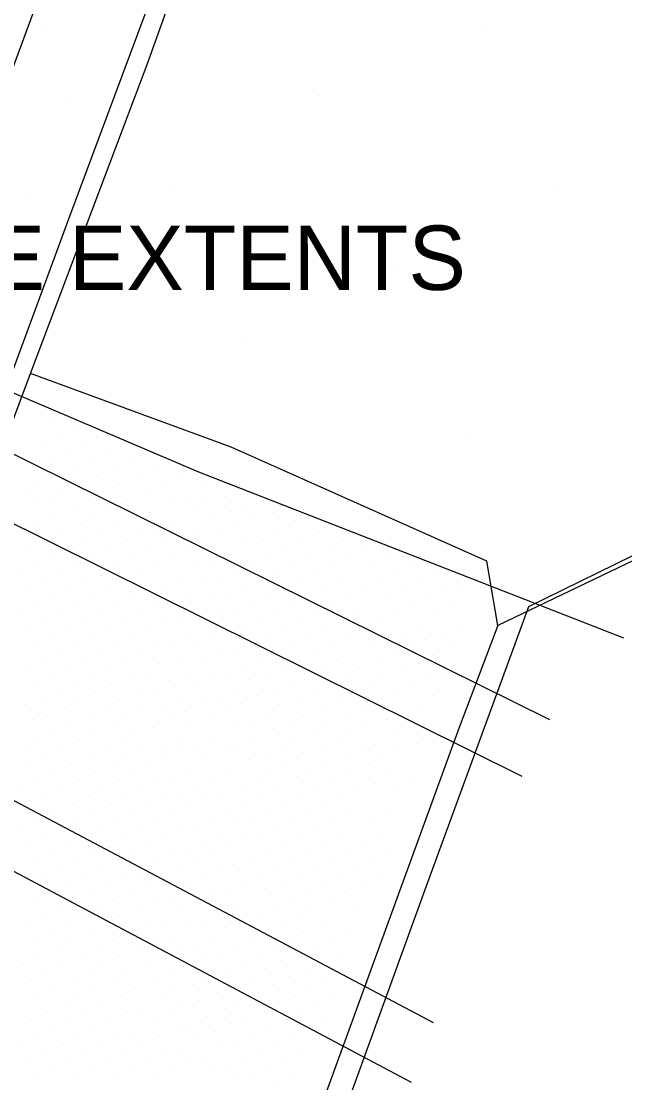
# Model space of a CAD drawing. Extents: x 1729983 to 1730242, y 468641 to 469019.
# Drawn here: x 1730163.18 to 1730180.05, y 468849.56 to 468879.25 of the extents above; entities that cross this region are included whole.
import ezdxf

# ---------------------------------------------------------------- set-up
doc = ezdxf.new("R2010")
doc.units = 0
for name, color, linetype in [('Default', 7, 'Continuous'), ('S_Bridge_Abutment_Bottom', 7, 'Continuous'), ('S_Curb_Type_1', 7, 'Continuous'), ('S_Ground_SpotElevation', 7, 'Continuous'), ('S_Misc_MiscFeature', 7, 'Continuous'), ('S_Roadway_Edge_Pavement', 7, 'Continuous'), ('S_Roadway_Painted_Lines', 7, 'Continuous'), ('S_Roadway_Sidewalks', 7, 'Continuous'), ('S_Text', 7, 'Continuous')]:
    doc.layers.add(name, color=color, linetype=linetype)

# ---------------------------------------------------------------- blocks, each defined once
blk = doc.blocks.new('POINT_DISPLAY')
at = {"layer": 'Default'}
blk.add_line((0, 0), (0, 0), dxfattribs=at)

msp = doc.modelspace()

# ---------------------------------------------------------------- linework, layer by layer
at = {"layer": 'S_Bridge_Abutment_Bottom'}
msp.add_lwpolyline([(1730181.425, 468864.71), (1730176.506, 468862.351), (1730175.427, 468859.495), (1730170.121, 468844.945), (1730162.576, 468824.377), (1730156.015, 468806.678), (1730146.892, 468781.991), (1730136.8, 468754.596), (1730127.192, 468728.47), (1730129.433, 468723.646)], dxfattribs=at)
at = {"layer": 'S_Curb_Type_1'}
msp.add_lwpolyline([(1730095.691, 468641.415), (1730095.909, 468646.136), (1730096.354, 468653.521), (1730096.818, 468653.995), (1730097.198, 468655.848), (1730096.66, 468657.036), (1730097.062, 468660.797), (1730098.243, 468671.757), (1730099.533, 468680.946), (1730101.556, 468692.14), (1730103.524, 468700.629), (1730106.497, 468712.327), (1730109.421, 468721.771), (1730114.404, 468736.003), (1730118.96, 468748.434), (1730124.347, 468762.755), (1730131.22, 468781.92), (1730136.349, 468795.804), (1730142.854, 468813.477), (1730149.849, 468832.496), (1730156.774, 468851.574), (1730163.434, 468869.402), (1730166.697, 468878.04), (1730172.479, 468894.171)], dxfattribs=at)
at = {"layer": 'S_Misc_MiscFeature'}
for p, q in [((1730150.177, 468873.465), (1730177.95, 468859.726)), ((1730177.188, 468858.129), (1730149.57, 468871.846)), ((1730147.288, 468865.747), (1730174.698, 468851.254)), ((1730174.087, 468849.573), (1730146.688, 468864.106))]:
    msp.add_line(p, q, dxfattribs=at)
for points in [[(1730180.027, 468861.998), (1730168.149, 468866.641), (1730159.874, 468870.164), (1730150.627, 468874.508)], [(1730180.75, 468864.535), (1730177.366, 468862.873), (1730174.461, 468854.957), (1730171.273, 468846.168), (1730167.811, 468836.657), (1730164.365, 468827.147), (1730154.502, 468800.309), (1730151.107, 468790.853), (1730144.524, 468772.905), (1730140.96, 468763.264), (1730137.54, 468754.064), (1730134.249, 468745.295), (1730130.903, 468736.495), (1730127.535, 468727.691), (1730129.089, 468724.341)]]:
    msp.add_lwpolyline(points, dxfattribs=at)
at = {"layer": 'S_Roadway_Edge_Pavement'}
msp.add_lwpolyline([(1730169.443, 468886.971), (1730164.503, 468873.715), (1730156.499, 468852.01), (1730147.717, 468828.276), (1730138.371, 468802.607), (1730128.942, 468777.012), (1730117.481, 468745.727), (1730111.874, 468730.709), (1730108.888, 468721.988), (1730105.794, 468711.827), (1730102.94, 468700.647), (1730101.123, 468692.177), (1730099.16, 468681.419), (1730097.818, 468671.805), (1730096.586, 468660.812), (1730096.168, 468657.103), (1730095.956, 468653.708), (1730095.867, 468652.572), (1730095.424, 468646.027), (1730095.252, 468641.367)], dxfattribs=at)
at = {"layer": 'S_Roadway_Painted_Lines'}
msp.add_lwpolyline([(1730094.799, 468656.256), (1730095.17, 468660.96), (1730096.083, 468669.985), (1730097.638, 468680.767), (1730099.581, 468691.95), (1730101.134, 468699.687), (1730104.772, 468714.073), (1730108.651, 468727.01), (1730112.542, 468738.83), (1730119.789, 468759.429), (1730137.203, 468807.807), (1730148.896, 468839.717), (1730160.486, 468871.271), (1730175.799, 468912.851), (1730190.41, 468952.883), (1730200.037, 468978.351)], dxfattribs=at)
at = {"layer": 'S_Roadway_Sidewalks'}
msp.add_lwpolyline([(1730176.506, 468862.351), (1730176.202, 468864.149), (1730169.049, 468867.338), (1730163.434, 468869.402)], dxfattribs=at)

# ---------------------------------------------------------------- block references
at = {"layer": 'S_Ground_SpotElevation'}
for p in [(1730163.786, 468879.057), (1730176.122, 468879.076), (1730171.509, 468877.18), (1730164.534, 468877.016), (1730167.412, 468874.677), (1730178.15, 468874.551), (1730163.449, 468874.405), (1730173.576, 468872.279), (1730169.407, 468870.366), (1730164.05, 468868.182), (1730164.634, 468867.892), (1730164.189, 468867.668), (1730165.293, 468867.636), (1730175.614, 468867.761), (1730163.742, 468867.455), (1730164.847, 468867.458), (1730166.041, 468867.438), (1730163.995, 468866.997), (1730164.461, 468867.167), (1730165.55, 468867.123), (1730166.634, 468867.123), (1730163.552, 468866.782), (1730164.674, 468866.729), (1730165.088, 468866.959), (1730165.719, 468866.713), (1730166.203, 468866.9), (1730167.315, 468866.882), (1730164.229, 468866.513), (1730165.273, 468866.52), (1730166.432, 468866.458), (1730166.856, 468866.694), (1730167.541, 468866.451), (1730167.965, 468866.659), (1730163.31, 468866.16), (1730163.639, 468866.347), (1730164.369, 468866.163), (1730164.868, 468866.272), (1730165.93, 468866.294), (1730167.083, 468866.257), (1730168.214, 468866.199), (1730169.248, 468866.168), (1730163.966, 468865.93), (1730165.056, 468865.834), (1730165.449, 468866.105), (1730166.16, 468865.842), (1730166.661, 468866.008), (1730167.796, 468865.97), (1730168.861, 468865.948), (1730163.509, 468865.75), (1730164.642, 468865.607), (1730165.672, 468865.668), (1730166.77, 468865.523), (1730167.336, 468865.782), (1730167.974, 468865.576), (1730168.325, 468865.774), (1730169.045, 468865.537), (1730169.474, 468865.718), (1730170.217, 468865.514), (1730163.679, 468865.267), (1730164.107, 468865.369), (1730165.211, 468865.457), (1730166.39, 468865.399), (1730167.464, 468865.266), (1730168.603, 468865.346), (1730169.661, 468865.306), (1730170.834, 468865.286), (1730163.183, 468865.034), (1730164.827, 468865.178), (1730165.389, 468864.983), (1730165.907, 468865.212), (1730167.022, 468865.045), (1730168.131, 468865.009), (1730169.24, 468865.106), (1730170.382, 468865.058), (1730171.53, 468864.965), (1730163.888, 468864.703), (1730164.302, 468864.916), (1730164.986, 468864.803), (1730166.149, 468864.75), (1730166.517, 468864.882), (1730167.202, 468864.64), (1730167.651, 468864.849), (1730168.81, 468864.9), (1730169.454, 468864.658), (1730169.952, 468864.77), (1730171.041, 468864.715), (1730172.196, 468864.754), (1730163.429, 468864.548), (1730164.111, 468864.331), (1730164.607, 468864.516), (1730165.22, 468864.35), (1730165.684, 468864.545), (1730166.759, 468864.426), (1730167.853, 468864.415), (1730168.326, 468864.587), (1730169.007, 468864.35), (1730170.152, 468864.348), (1730170.579, 468864.557), (1730171.22, 468864.327), (1730171.765, 468864.572), (1730172.822, 468864.408), (1730163.623, 468864.103), (1730165.805, 468864.04), (1730166.283, 468864.231), (1730166.939, 468864.029), (1730167.383, 468864.234), (1730168.532, 468864.147), (1730169.718, 468864.137), (1730170.815, 468864.125), (1730171.859, 468864.101), (1730172.323, 468864.285), (1730172.984, 468864.046), (1730173.513, 468864.289), (1730163.185, 468863.909), (1730164.277, 468863.809), (1730164.726, 468864.01), (1730165.418, 468863.761), (1730166.536, 468863.758), (1730168.048, 468863.989), (1730169.224, 468863.87), (1730170.335, 468863.952), (1730171.519, 468863.803), (1730173.731, 468863.842), (1730174.161, 468864.018), (1730174.783, 468863.772), (1730163.369, 468863.479), (1730163.833, 468863.629), (1730164.946, 468863.582), (1730166.065, 468863.562), (1730167.226, 468863.495), (1730167.676, 468863.695), (1730168.339, 468863.55), (1730168.75, 468863.694), (1730169.364, 468863.494), (1730169.962, 468863.685), (1730170.967, 468863.698), (1730172.15, 468863.575), (1730173.221, 468863.568), (1730174.372, 468863.591), (1730175.424, 468863.494), (1730164.015, 468863.213), (1730164.452, 468863.389), (1730165.57, 468863.408), (1730166.729, 468863.338), (1730167.89, 468863.246), (1730168.983, 468863.212), (1730170.098, 468863.242), (1730170.53, 468863.362), (1730171.265, 468863.193), (1730171.656, 468863.364), (1730172.794, 468863.38), (1730173.841, 468863.354), (1730174.996, 468863.353), (1730163.56, 468863.044), (1730164.669, 468862.992), (1730165.18, 468863.134), (1730165.835, 468862.917), (1730166.323, 468863.083), (1730166.913, 468862.933), (1730167.444, 468863.039), (1730168.523, 468863.067), (1730169.595, 468863.026), (1730170.684, 468862.988), (1730171.926, 468862.948), (1730172.393, 468863.111), (1730173.46, 468863.099), (1730174.069, 468862.894), (1730174.611, 468863.117), (1730175.231, 468862.894), (1730163.184, 468862.77), (1730164.262, 468862.734), (1730165.357, 468862.742), (1730166.522, 468862.655), (1730167.66, 468862.585), (1730168.096, 468862.807), (1730168.684, 468862.644), (1730169.204, 468862.761), (1730169.817, 468862.572), (1730170.235, 468862.798), (1730171.486, 468862.75), (1730172.477, 468862.715), (1730173.659, 468862.635), (1730174.721, 468862.638), (1730163.386, 468862.309), (1730163.83, 468862.516), (1730164.509, 468862.263), (1730164.923, 468862.517), (1730166.093, 468862.437), (1730166.707, 468862.25), (1730167.132, 468862.476), (1730168.342, 468862.434), (1730169.426, 468862.297), (1730170.469, 468862.328), (1730170.922, 468862.514), (1730172.05, 468862.435), (1730173.19, 468862.499), (1730174.334, 468862.385), (1730175.479, 468862.334), (1730163.993, 468862.128), (1730165.121, 468862.094), (1730165.631, 468862.234), (1730166.277, 468862.037), (1730167.88, 468862.127), (1730168.446, 468861.973), (1730168.916, 468862.171), (1730170.067, 468862.081), (1730171.162, 468862.04), (1730171.63, 468862.211), (1730172.279, 468861.97), (1730172.796, 468862.184), (1730173.444, 468862.005), (1730173.81, 468862.165), (1730174.464, 468861.951), (1730174.99, 468862.124), (1730163.564, 468861.891), (1730164.676, 468861.88), (1730165.8, 468861.861), (1730166.898, 468861.843), (1730167.437, 468861.93), (1730168.092, 468861.763), (1730169.159, 468861.687), (1730169.573, 468861.848), (1730170.745, 468861.799), (1730171.878, 468861.839), (1730172.959, 468861.862), (1730174.048, 468861.815), (1730175.204, 468861.737), (1730163.812, 468861.404), (1730164.247, 468861.642), (1730164.948, 468861.385), (1730165.386, 468861.608), (1730166.428, 468861.569), (1730167.65, 468861.485), (1730168.694, 468861.499), (1730169.794, 468861.465), (1730170.25, 468861.638), (1730170.958, 468861.401), (1730171.407, 468861.553), (1730172.004, 468861.385), (1730173.682, 468861.531), (1730174.674, 468861.518), (1730163.353, 468861.195), (1730164.5, 468861.157), (1730165.526, 468861.093), (1730165.987, 468861.28), (1730167.052, 468861.296), (1730168.223, 468861.329), (1730169.412, 468861.25), (1730170.447, 468861.236), (1730171.544, 468861.202), (1730172.649, 468861.148), (1730173.244, 468861.342), (1730173.824, 468861.169), (1730174.282, 468861.289), (1730163.969, 468861.032), (1730164.667, 468860.781), (1730165.084, 468860.863), (1730166.195, 468860.85), (1730166.651, 468861.042), (1730167.287, 468860.818), (1730167.828, 468861.027), (1730168.461, 468860.856), (1730168.926, 468861.035), (1730169.534, 468860.847), (1730170.033, 468860.988), (1730171.106, 468861), (1730172.265, 468860.888), (1730173.322, 468860.89), (1730174.555, 468860.835), (1730174.991, 468861.019), (1730163.573, 468860.752), (1730164.2, 468860.578), (1730165.257, 468860.482), (1730165.711, 468860.696), (1730166.865, 468860.599), (1730168.005, 468860.67), (1730169.178, 468860.536), (1730170.287, 468860.496), (1730170.707, 468860.733), (1730171.349, 468860.532), (1730171.787, 468860.732), (1730172.993, 468860.697), (1730174.013, 468860.68), (1730163.81, 468860.28), (1730164.793, 468860.277), (1730165.926, 468860.255), (1730166.399, 468860.428), (1730167.525, 468860.336), (1730168.247, 468860.19), (1730168.731, 468860.333), (1730169.316, 468860.177), (1730169.768, 468860.385), (1730170.943, 468860.264), (1730172.061, 468860.225), (1730172.515, 468860.413), (1730173.135, 468860.217), (1730173.551, 468860.439), (1730174.685, 468860.389), (1730163.283, 468860.147), (1730164.38, 468860.043), (1730165.543, 468859.967), (1730166.603, 468860.001), (1730167.093, 468860.136), (1730167.757, 468859.945), (1730168.902, 468859.942), (1730170.022, 468859.932), (1730170.403, 468860.129), (1730171.62, 468860.016), (1730172.683, 468860.031), (1730173.831, 468859.921), (1730174.232, 468860.121), (1730163.496, 468859.713), (1730163.907, 468859.801), (1730164.557, 468859.62), (1730165.058, 468859.787), (1730166.118, 468859.735), (1730167.323, 468859.71), (1730168.488, 468859.715), (1730169.566, 468859.687), (1730170.665, 468859.669), (1730171.06, 468859.795), (1730172.242, 468859.815), (1730173.391, 468859.733), (1730164.117, 468859.387), (1730165.221, 468859.415), (1730165.737, 468859.556), (1730166.378, 468859.311), (1730166.854, 468859.504), (1730167.904, 468859.496), (1730169.087, 468859.535), (1730170.206, 468859.466), (1730171.317, 468859.453), (1730171.72, 468859.53), (1730172.399, 468859.288), (1730172.816, 468859.545), (1730174.045, 468859.501), (1730163.314, 468859.002), (1730163.63, 468859.2), (1730164.806, 468859.151), (1730165.947, 468859.114), (1730167.094, 468859.024), (1730167.532, 468859.212), (1730168.157, 468859.003), (1730168.591, 468859.215), (1730169.221, 468858.993), (1730169.705, 468859.144), (1730170.456, 468858.982), (1730170.8, 468859.129), (1730172.011, 468859.19), (1730173.092, 468859.024), (1730173.608, 468859.278), (1730174.239, 468859.049), (1730163.895, 468858.73), (1730164.333, 468858.962), (1730165.535, 468858.856), (1730166.572, 468858.914), (1730167.66, 468858.869), (1730168.874, 468858.863), (1730170.002, 468858.776), (1730171.082, 468858.798), (1730171.576, 468858.963), (1730172.692, 468858.953), (1730173.713, 468858.815), (1730163.408, 468858.546), (1730164.572, 468858.496), (1730165.07, 468858.657), (1730165.734, 468858.426), (1730166.159, 468858.665), (1730166.818, 468858.42), (1730167.25, 468858.635), (1730168.337, 468858.622), (1730169.525, 468858.616), (1730170.593, 468858.44), (1730171.681, 468858.475), (1730172.24, 468858.627), (1730172.877, 468858.506), (1730173.321, 468858.659), (1730164.094, 468858.318), (1730165.252, 468858.254), (1730166.384, 468858.201), (1730167.464, 468858.122), (1730167.917, 468858.366), (1730169.005, 468858.331), (1730169.778, 468858.128), (1730170.119, 468858.27), (1730170.867, 468858.123), (1730171.208, 468858.27), (1730172.342, 468858.25), (1730173.456, 468858.171), (1730163.219, 468857.859), (1730163.674, 468858.073), (1730164.303, 468857.889), (1730164.801, 468858.048), (1730165.915, 468858.024), (1730167.02, 468857.945), (1730168.079, 468857.866), (1730168.602, 468858.08), (1730169.315, 468857.89), (1730170.362, 468857.808), (1730171.957, 468857.973), (1730173.074, 468857.946), (1730174.102, 468857.946), (1730163.887, 468857.642), (1730165.061, 468857.561), (1730165.489, 468857.773), (1730166.122, 468857.586), (1730166.604, 468857.745), (1730167.202, 468857.569), (1730167.696, 468857.648), (1730168.312, 468857.518), (1730168.767, 468857.632), (1730169.882, 468857.641), (1730171.005, 468857.593), (1730171.473, 468857.788), (1730172.203, 468857.549), (1730172.563, 468857.71), (1730173.685, 468857.765), (1730163.418, 468857.448), (1730164.611, 468857.345), (1730165.699, 468857.352), (1730166.737, 468857.34), (1730167.883, 468857.3), (1730169.024, 468857.206), (1730169.429, 468857.449), (1730170.597, 468857.424), (1730171.737, 468857.307), (1730163.644, 468856.996), (1730164.12, 468857.175), (1730164.668, 468856.915), (1730165.261, 468857.166), (1730166.333, 468857.135), (1730167.436, 468857.098), (1730168.59, 468857.003), (1730169.705, 468856.942), (1730170.122, 468857.188), (1730170.762, 468856.978), (1730171.26, 468857.12), (1730171.848, 468856.94), (1730172.39, 468857.092), (1730173.405, 468857.09), (1730163.198, 468856.778), (1730164.338, 468856.742), (1730165.36, 468856.646), (1730165.811, 468856.839), (1730166.577, 468856.636), (1730166.979, 468856.9), (1730168.143, 468856.799), (1730169.166, 468856.81), (1730170.349, 468856.666), (1730171.452, 468856.669), (1730173.051, 468856.882), (1730163.881, 468856.528), (1730164.895, 468856.472), (1730166.13, 468856.446), (1730167.197, 468856.447), (1730167.694, 468856.594), (1730168.715, 468856.542), (1730169.424, 468856.376), (1730169.882, 468856.559), (1730170.555, 468856.312), (1730171.007, 468856.517), (1730171.646, 468856.316), (1730172.104, 468856.387), (1730173.263, 468856.42), (1730163.367, 468856.215), (1730164.514, 468856.176), (1730165.608, 468856.163), (1730166.797, 468856.178), (1730167.785, 468856.112), (1730168.263, 468856.284), (1730168.98, 468856.17), (1730170.142, 468856.069), (1730171.128, 468856.017), (1730172.327, 468856.063), (1730172.722, 468856.231), (1730163.59, 468855.77), (1730164.048, 468855.975), (1730164.649, 468855.833), (1730165.165, 468855.956), (1730165.889, 468855.807), (1730166.302, 468855.931), (1730167.004, 468855.737), (1730167.431, 468855.978), (1730168.073, 468855.763), (1730168.547, 468855.944), (1730169.678, 468855.901), (1730170.682, 468855.808), (1730171.789, 468855.789), (1730173.047, 468855.749), (1730173.377, 468856), (1730164.238, 468855.522), (1730165.318, 468855.587), (1730166.474, 468855.456), (1730167.668, 468855.497), (1730168.785, 468855.482), (1730169.098, 468855.662), (1730170.262, 468855.572), (1730171.414, 468855.5), (1730172.481, 468855.513), (1730163.293, 468855.213), (1730163.831, 468855.31), (1730164.444, 468855.142), (1730164.93, 468855.304), (1730165.99, 468855.306), (1730167.123, 468855.225), (1730168.318, 468855.286), (1730169.359, 468855.179), (1730169.831, 468855.352), (1730170.434, 468855.189), (1730170.968, 468855.367), (1730171.577, 468855.132), (1730172.073, 468855.276), (1730172.697, 468855.142), (1730173.167, 468855.356), (1730163.959, 468854.981), (1730165.111, 468854.889), (1730165.541, 468855.109), (1730166.213, 468854.826), (1730166.762, 468855.099), (1730167.737, 468855.039), (1730168.884, 468854.992), (1730169.983, 468854.983), (1730171.151, 468854.901), (1730172.226, 468854.914), (1730163.572, 468854.731), (1730164.62, 468854.743), (1730165.739, 468854.671), (1730166.85, 468854.593), (1730167.337, 468854.775), (1730168.036, 468854.603), (1730168.482, 468854.823), (1730170.702, 468854.697), (1730171.831, 468854.602), (1730163.736, 468854.327), (1730164.198, 468854.516), (1730165.335, 468854.407), (1730166.471, 468854.344), (1730167.537, 468854.35), (1730168.619, 468854.368), (1730169.168, 468854.466), (1730169.796, 468854.28), (1730170.258, 468854.483), (1730170.887, 468854.297), (1730171.307, 468854.486), (1730172.495, 468854.349), (1730163.327, 468854.073), (1730164.458, 468854.019), (1730164.912, 468854.193), (1730165.528, 468853.978), (1730165.938, 468854.228), (1730166.652, 468853.935), (1730167.133, 468854.095), (1730167.839, 468853.957), (1730168.267, 468854.051), (1730169.31, 468854.111), (1730170.423, 468854.048), (1730163.958, 468853.882), (1730165.107, 468853.763), (1730166.242, 468853.68), (1730167.335, 468853.668), (1730168.856, 468853.91), (1730170.089, 468853.851), (1730171.083, 468853.805), (1730171.546, 468853.934), (1730172.302, 468853.717), (1730163.542, 468853.637), (1730164.192, 468853.42), (1730164.57, 468853.552), (1730165.728, 468853.55), (1730166.874, 468853.477), (1730168.022, 468853.399), (1730168.48, 468853.61), (1730169.137, 468853.381), (1730169.563, 468853.622), (1730170.22, 468853.418), (1730170.719, 468853.578), (1730171.337, 468853.406), (1730171.842, 468853.534), (1730163.657, 468853.131), (1730164.906, 468853.088), (1730165.304, 468853.334), (1730165.928, 468853.121), (1730166.433, 468853.26), (1730167.525, 468853.251), (1730168.698, 468853.169), (1730169.829, 468853.126), (1730170.881, 468853.203), (1730172.005, 468853.16), (1730163.256, 468852.865), (1730164.331, 468852.881), (1730165.476, 468852.936), (1730166.656, 468852.798), (1730167.088, 468853.026), (1730167.728, 468852.822), (1730168.189, 468853.026), (1730169.374, 468852.913), (1730169.979, 468852.752), (1730170.428, 468852.976), (1730171.508, 468852.833), (1730163.858, 468852.72), (1730164.641, 468852.475), (1730165.081, 468852.686), (1730166.118, 468852.637), (1730167.293, 468852.588), (1730168.369, 468852.52), (1730168.852, 468852.741), (1730169.584, 468852.543), (1730170.651, 468852.542), (1730171.17, 468852.681), (1730163.465, 468852.442), (1730164.104, 468852.244), (1730165.783, 468852.375), (1730166.363, 468852.208), (1730166.873, 468852.343), (1730167.493, 468852.171), (1730167.975, 468852.305), (1730169.128, 468852.282), (1730170.215, 468852.307), (1730171.689, 468852.433), (1730163.671, 468852.022), (1730164.752, 468851.981), (1730165.233, 468852.128), (1730165.948, 468851.991), (1730167.098, 468851.884), (1730168.169, 468851.867), (1730168.626, 468852.087), (1730169.802, 468852.063), (1730170.849, 468851.978), (1730171.307, 468852.147), (1730171.89, 468852.002), (1730164.397, 468851.824), (1730164.975, 468851.566), (1730165.39, 468851.744), (1730166.138, 468851.57), (1730166.564, 468851.638), (1730167.704, 468851.73), (1730168.861, 468851.65), (1730169.211, 468851.811), (1730171.499, 468851.724), (1730163.473, 468851.344), (1730163.918, 468851.545), (1730164.552, 468851.307), (1730167.316, 468851.439), (1730168.377, 468851.429), (1730169.409, 468851.406), (1730169.989, 468851.548), (1730170.611, 468851.327), (1730171.022, 468851.551), (1730171.685, 468851.311), (1730164.061, 468851.182), (1730165.175, 468851.089), (1730165.643, 468851.228), (1730166.327, 468850.972), (1730166.858, 468851.251), (1730167.507, 468851.038), (1730167.84, 468851.205), (1730168.618, 468850.996), (1730169.055, 468851.215), (1730170.158, 468851.073), (1730171.334, 468851.117), (1730163.184, 468850.76), (1730163.628, 468850.945), (1730164.783, 468850.886), (1730165.837, 468850.831), (1730167.04, 468850.856), (1730168.05, 468850.772), (1730169.205, 468850.725), (1730169.663, 468850.874), (1730170.756, 468850.938), (1730163.892, 468850.462), (1730164.358, 468850.621), (1730164.967, 468850.429), (1730165.452, 468850.576), (1730166.473, 468850.615), (1730167.626, 468850.535), (1730168.783, 468850.548), (1730169.856, 468850.523), (1730170.37, 468850.657), (1730171.049, 468850.396), (1730163.346, 468850.195), (1730164.52, 468850.231), (1730165.623, 468850.186), (1730166.111, 468850.324), (1730166.763, 468850.091), (1730167.17, 468850.321), (1730167.813, 468850.133), (1730168.29, 468850.302), (1730168.987, 468850.088), (1730169.445, 468850.221), (1730170.591, 468850.209), (1730163.671, 468849.845), (1730164.05, 468850.073), (1730165.243, 468849.923), (1730166.252, 468849.978), (1730167.405, 468849.885), (1730168.505, 468849.868), (1730169.64, 468849.786), (1730170.069, 468850), (1730170.766, 468849.792), (1730164.774, 468849.747), (1730165.9, 468849.672), (1730166.912, 468849.737), (1730169.156, 468849.667), (1730170.285, 468849.575)]:
    msp.add_blockref('POINT_DISPLAY', p, dxfattribs=at)

# ---------------------------------------------------------------- texts
at = {"layer": 'S_Text'}
msp.add_text('BRIDGE EXTENTS', height=1.8, dxfattribs=at).set_placement((1730154.614, 468871.735))

doc.saveas('drawing.dxf')
